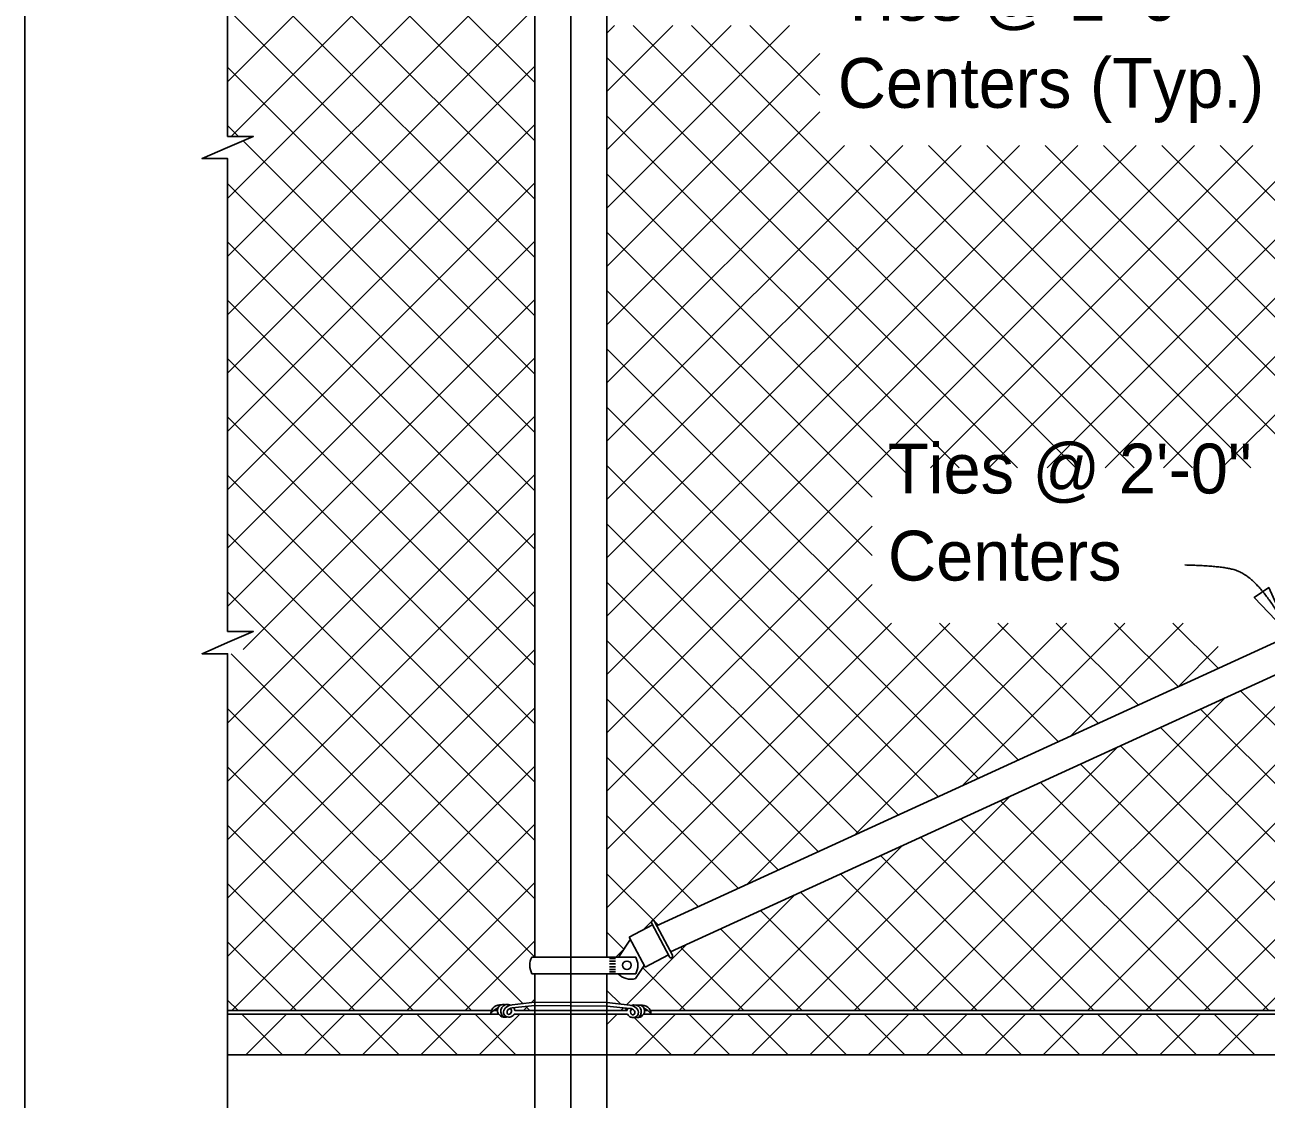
# Model space of a CAD drawing. Extents: x 0 to 41.2, y 0 to 26.
# Drawn here: x 0 to 5.02, y 17.29 to 21.63 of the extents above; entities that cross this region are included whole.
import ezdxf

# ---------------------------------------------------------------- set-up
doc = ezdxf.new("R2010")
doc.units = 0
for name, color, linetype in [('ActivePts-ConstElements', 7, 'Continuous'), ('CL_Major', 7, 'Continuous'), ('Dimension', 7, 'Continuous'), ('Miscellaneous', 7, 'Continuous'), ('Miscellaneous1', 7, 'Continuous'), ('SteelMisc', 7, 'Continuous'), ('SteelMisc_h', 7, 'Continuous'), ('SupstrConc', 7, 'Continuous'), ('TextStructures', 7, 'Continuous')]:
    doc.layers.add(name, color=color, linetype=linetype)

msp = doc.modelspace()

# ---------------------------------------------------------------- linework, layer by layer
at = {"layer": 'ActivePts-ConstElements'}
msp.add_lwpolyline([(0, 0), (41.2106, 0), (41.2106, 25.96), (0, 25.96)], close=True, dxfattribs=at)
at = {"layer": 'CL_Major'}
msp.add_line((2.2062, 25.6784), (2.2062, 14.8533), dxfattribs=at)
at = {"layer": 'Dimension'}
for points in [[(0.8194, 24.349), (0.8194, 21.1819), (0.9227, 21.1819), (0.8194, 21.1369), (0.716, 21.0919), (0.8194, 21.0919), (0.8194, 20.1983)], [(0.8194, 20.1983), (0.8194, 19.1806), (0.9227, 19.1806), (0.8194, 19.1356), (0.716, 19.0906), (0.8194, 19.0906), (0.8194, 16.8862)]]:
    msp.add_lwpolyline(points, dxfattribs=at)
msp.add_lwpolyline([(5.1135, 19.1655), (5.0266, 19.358), (4.968, 19.3186)], close=True, dxfattribs=at)
msp.add_open_spline([(4.6876, 19.4494), (4.8459, 19.4462), (4.9517, 19.4061), (5.0648, 19.263), (5.1136, 19.1655)], degree=2, dxfattribs=at)
at = {"layer": 'Miscellaneous'}
for p, q in [((1.8028, 22.3863), (0.8192, 21.4028)), ((2.0603, 21.1639), (0.8381, 22.3861)), ((2.0603, 21.3996), (1.0738, 22.3862)), ((6.6782, 22.39), (4.1304, 19.8423)), ((6.9139, 22.39), (4.3661, 19.8423)), ((7.1496, 22.39), (4.6018, 19.8423)), ((7.3853, 22.39), (4.8375, 19.8423)), ((2.0163, 22.3642), (0.8341, 21.1819)), ((2.0603, 22.1725), (0.8192, 20.9314)), ((2.0603, 20.9282), (0.8192, 22.1693)), ((2.0603, 21.9368), (0.8192, 20.6957)), ((2.0603, 20.6925), (0.8192, 21.9336)), ((2.0603, 21.701), (0.8192, 20.46)), ((2.0603, 20.4568), (0.8192, 21.6979)), ((2.6187, 21.6304), (2.352, 21.3636)), ((2.383, 21.6304), (2.352, 21.5993)), ((2.8544, 21.6304), (2.352, 21.1279)), ((3.0901, 21.6304), (2.352, 20.8922)), ((4.2468, 19.8423), (2.4587, 21.6304)), ((4.4825, 19.8423), (2.6944, 21.6304)), ((3.2122, 21.3482), (2.9301, 21.6304)), ((3.2122, 21.5167), (2.352, 20.6565)), ((4.011, 19.8423), (2.352, 21.5013)), ((2.0603, 21.4653), (0.8192, 20.2243)), ((2.0603, 20.2211), (0.8192, 21.4622)), ((3.2122, 21.281), (2.352, 20.4208)), ((2.0603, 21.2296), (0.8192, 19.9886)), ((0.8638, 21.1819), (0.8192, 21.2265)), ((3.7753, 19.8423), (2.352, 21.2656)), ((2.0603, 19.9854), (0.8817, 21.164)), ((4.2544, 21.1447), (2.352, 19.2423)), ((3.783, 21.1447), (2.352, 19.7137)), ((3.3116, 21.1447), (2.352, 20.1851)), ((3.5473, 21.1447), (2.352, 19.9494)), ((4.0187, 21.1447), (2.352, 19.478)), ((4.4901, 21.1447), (2.352, 19.0066)), ((4.7182, 19.8423), (3.4157, 21.1447)), ((4.7258, 21.1447), (3.4233, 19.8423)), ((4.9539, 19.8423), (3.6514, 21.1447)), ((4.9615, 21.1447), (3.659, 19.8423)), ((5.1896, 19.8423), (3.8871, 21.1447)), ((5.1972, 21.1447), (3.8947, 19.8423)), ((5.4253, 19.8423), (4.1228, 21.1447)), ((5.9529, 19.5503), (4.3585, 21.1447)), ((6.1145, 19.6244), (4.5942, 21.1447)), ((6.2762, 19.6985), (4.8299, 21.1447)), ((3.5642, 19.8177), (2.352, 21.0299)), ((2.0603, 20.9939), (0.8192, 19.7529)), ((2.0603, 19.7497), (0.8192, 20.9908)), ((3.4233, 19.7229), (2.352, 20.7942)), ((2.0603, 20.7582), (0.8192, 19.5171)), ((2.0603, 19.514), (0.8192, 20.7551)), ((2.0603, 20.5225), (0.8192, 19.2814)), ((2.0603, 19.2783), (0.8192, 20.5194)), ((3.4233, 19.4872), (2.352, 20.5585)), ((4.0136, 18.6612), (2.352, 20.3228)), ((2.0603, 19.0426), (0.8192, 20.2837)), ((2.0603, 20.2868), (0.8817, 19.1083)), ((3.852, 18.5871), (2.352, 20.0871)), ((7.463, 20.1106), (5.0009, 17.6486)), ((2.0603, 20.0511), (0.8192, 18.81)), ((2.0603, 18.8069), (0.8192, 20.048)), ((7.0277, 19.9111), (4.7652, 17.6486)), ((2.0603, 19.8154), (0.8192, 18.5743)), ((3.6903, 18.513), (2.352, 19.8514)), ((3.4233, 19.8423), (2.352, 18.7709)), ((2.0603, 18.5712), (0.8192, 19.8123)), ((6.5925, 19.7116), (4.5295, 17.6486)), ((3.5287, 18.439), (2.352, 19.6157)), ((2.0603, 19.5797), (0.8192, 18.3386)), ((2.0603, 18.3355), (0.8192, 19.5766)), ((3.4233, 19.6066), (2.352, 18.5352)), ((6.1573, 19.5121), (4.2938, 17.6486)), ((3.3671, 18.3649), (2.352, 19.38)), ((3.4233, 19.3709), (2.352, 18.2995)), ((2.0603, 19.344), (0.8192, 18.1029)), ((2.0603, 18.0998), (0.8192, 19.3409)), ((5.7221, 19.3126), (4.0581, 17.6486)), ((3.5027, 19.2146), (2.352, 18.0638)), ((3.7384, 19.2146), (2.4979, 17.974)), ((3.9741, 19.2146), (2.919, 18.1595)), ((4.2098, 19.2146), (3.3543, 18.359)), ((4.1752, 18.7353), (3.6959, 19.2146)), ((4.4455, 19.2146), (3.7895, 18.5585)), ((4.3368, 18.8094), (3.9317, 19.2146)), ((4.4984, 18.8835), (4.1674, 19.2146)), ((4.6812, 19.2146), (4.2247, 18.758)), ((4.66, 18.9576), (4.4031, 19.2146)), ((4.8216, 19.0317), (4.6388, 19.2146)), ((3.2055, 18.2908), (2.352, 19.1443)), ((5.2869, 19.1131), (3.8224, 17.6486)), ((4.8227, 19.1203), (4.6599, 18.9575)), ((2.0603, 19.1083), (0.8192, 17.8672)), ((2.0603, 17.8641), (0.8339, 19.0905)), ((4.8517, 18.9136), (3.5867, 17.6486)), ((6.2048, 17.6486), (4.912, 18.9413)), ((2.012, 17.6767), (0.8192, 18.8695)), ((2.0603, 18.8726), (0.8363, 17.6486)), ((3.0439, 18.2167), (2.352, 18.9086)), ((5.9691, 17.6486), (4.7504, 18.8672)), ((5.7333, 17.6486), (4.5888, 18.7931)), ((4.4165, 18.7141), (3.3509, 17.6486)), ((5.4976, 17.6486), (4.4272, 18.719)), ((2.8823, 18.1426), (2.352, 18.6729)), ((1.8044, 17.6486), (0.8192, 18.6338)), ((2.0603, 18.6369), (1.072, 17.6486)), ((5.2619, 17.6486), (4.2656, 18.6449)), ((5.0262, 17.6486), (4.104, 18.5708)), ((3.9813, 18.5146), (3.1152, 17.6486)), ((4.7905, 17.6486), (3.9424, 18.4967)), ((2.7207, 18.0685), (2.352, 18.4372)), ((4.5548, 17.6486), (3.7807, 18.4227)), ((1.5687, 17.6486), (0.8192, 18.3981)), ((2.0603, 18.4012), (1.3077, 17.6486)), ((3.5461, 18.3151), (2.8795, 17.6486)), ((4.3191, 17.6486), (3.6191, 18.3486)), ((4.0834, 17.6486), (3.4575, 18.2745)), ((1.333, 17.6486), (0.8192, 18.1624)), ((2.0603, 18.1655), (1.5434, 17.6486)), ((2.5591, 17.9944), (2.352, 18.2015)), ((3.8477, 17.6486), (3.2959, 18.2004)), ((3.1108, 18.1156), (2.6438, 17.6486)), ((3.612, 17.6486), (3.1343, 18.1263)), ((3.3763, 17.6486), (2.9727, 18.0522)), ((2.4208, 17.897), (2.352, 17.9658)), ((3.1406, 17.6486), (2.8111, 17.9781)), ((1.0973, 17.6486), (0.8192, 17.9267)), ((2.0603, 17.9298), (1.7791, 17.6486)), ((2.6756, 17.9161), (2.4309, 17.6713)), ((2.4207, 17.8968), (2.3885, 17.8646)), ((2.9049, 17.6486), (2.6494, 17.904)), ((2.6692, 17.6486), (2.4966, 17.8212)), ((2.4079, 17.6742), (2.352, 17.7301)), ((0.8616, 17.6486), (0.8192, 17.691)), ((2.0315, 17.6653), (2.0148, 17.6486)), ((2.0401, 17.6486), (2.0242, 17.6645)), ((2.0603, 17.6941), (2.0474, 17.6812)), ((2.4193, 17.6597), (2.4081, 17.6486)), ((2.4335, 17.6486), (2.4228, 17.6593)), ((0.8215, 17.6338), (0.8192, 17.6315)), ((1.0409, 17.4693), (0.8764, 17.6338)), ((1.0572, 17.6338), (0.8927, 17.4693)), ((1.2766, 17.4693), (1.1121, 17.6338)), ((1.2929, 17.6338), (1.1284, 17.4693)), ((1.5123, 17.4693), (1.3478, 17.6338)), ((1.5286, 17.6338), (1.3641, 17.4693)), ((1.748, 17.4693), (1.5835, 17.6338)), ((1.7643, 17.6338), (1.5998, 17.4693)), ((1.9837, 17.4693), (1.8192, 17.6338)), ((2, 17.6338), (1.8355, 17.4693)), ((2.0603, 17.6284), (2.0549, 17.6338)), ((2.3934, 17.6338), (2.352, 17.5924)), ((2.6127, 17.4693), (2.4617, 17.6203)), ((2.6291, 17.6338), (2.4646, 17.4693)), ((2.8484, 17.4693), (2.684, 17.6338)), ((2.8648, 17.6338), (2.7003, 17.4693)), ((3.0842, 17.4693), (2.9197, 17.6338)), ((3.1005, 17.6338), (2.936, 17.4693)), ((3.3199, 17.4693), (3.1554, 17.6338)), ((3.3362, 17.6338), (3.1717, 17.4693)), ((3.5556, 17.4693), (3.3911, 17.6338)), ((3.5719, 17.6338), (3.4074, 17.4693)), ((3.7913, 17.4693), (3.6268, 17.6338)), ((3.8076, 17.6338), (3.6431, 17.4693)), ((4.027, 17.4693), (3.8625, 17.6338)), ((4.0433, 17.6338), (3.8788, 17.4693)), ((4.2627, 17.4693), (4.0982, 17.6338)), ((4.279, 17.6338), (4.1145, 17.4693)), ((4.4984, 17.4693), (4.3339, 17.6338)), ((4.5147, 17.6338), (4.3502, 17.4693)), ((4.7341, 17.4693), (4.5696, 17.6338)), ((4.7504, 17.6338), (4.5859, 17.4693)), ((4.9698, 17.4693), (4.8053, 17.6338)), ((4.9861, 17.6338), (4.8216, 17.4693))]:
    msp.add_line(p, q, dxfattribs=at)
at = {"layer": 'Miscellaneous1'}
msp.add_lwpolyline([(0, 25.96), (41.2106, 25.96), (41.2106, 0), (0, 0)], close=True, dxfattribs=at)
at = {"layer": 'SteelMisc'}
for p, q in [((2.0603, 17.8646), (2.0603, 24.349)), ((2.352, 17.8646), (2.352, 24.349)), ((2.5526, 17.9915), (11.8021, 22.2317)), ((2.6096, 17.8858), (11.8582, 22.1255)), ((2.6171, 17.8717), (2.5446, 18.0088)), ((2.5369, 17.9947), (2.4426, 17.9448)), ((2.6052, 17.8654), (2.5328, 18.0026)), ((2.4468, 17.9368), (2.3999, 17.8651)), ((2.5063, 17.8242), (2.4426, 17.9448)), ((2.049, 17.8646), (2.4687, 17.8646)), ((2.3864, 17.8584), (2.3629, 17.8584)), ((2.5063, 17.8242), (2.6006, 17.8741)), ((2.3864, 17.8486), (2.3629, 17.8486)), ((2.3864, 17.8368), (2.3629, 17.8368)), ((2.3864, 17.825), (2.3629, 17.825)), ((2.3864, 17.8142), (2.3629, 17.8142)), ((2.5029, 17.8308), (2.4681, 17.7777)), ((2.0491, 17.7968), (2.4687, 17.7968)), ((2.0603, 17.0944), (2.0603, 17.7968)), ((2.352, 17.0944), (2.352, 17.7968)), ((2.3864, 17.8046), (2.3629, 17.8046)), ((2.0608, 17.6829), (1.9689, 17.6713)), ((2.0608, 17.6683), (1.9689, 17.6588)), ((2.352, 17.6812), (2.0608, 17.6829)), ((2.352, 17.6667), (2.0608, 17.6683)), ((2.352, 17.6812), (2.4449, 17.6695)), ((2.352, 17.6667), (2.4448, 17.657)), ((1.8859, 17.6486), (0.8192, 17.6486)), ((1.9145, 17.6338), (0.8192, 17.6338)), ((1.9096, 17.6486), (1.8943, 17.6486)), ((2.0603, 17.6338), (1.9773, 17.6338)), ((2.0603, 17.6486), (1.9799, 17.6486)), ((2.4342, 17.6486), (2.352, 17.6486)), ((2.4356, 17.6338), (2.352, 17.6338)), ((11.8982, 17.6338), (2.5005, 17.6338)), ((2.5172, 17.6486), (2.5041, 17.6486)), ((11.8969, 17.6486), (2.5271, 17.6486))]:
    msp.add_line(p, q, dxfattribs=at)
for centre, start, end in [((2.5385, 18.0058), 27.851, 207.851), ((2.611, 17.8686), 207.851, 27.851)]:
    msp.add_arc(centre, 0.00673, start, end, dxfattribs=at)
for centre, major_axis, ratio, start_param, end_param in [((2.1181, 17.8309), (-0.0776, 0), 0.957868, 5.811591, 6.758603), ((2.3995, 17.8309), (0.0776, 0), 0.957868, 5.810211, 6.75616), ((2.4515, 17.846), (-0.0647, -0.0342), 0.957868, 0.271397, 1.331255), ((1.9209, 17.6361), (0.0373, 0), 0.957868, 1.427863, 3.108042), ((1.942, 17.5964), (-0.0724, 0), 0.957868, 5.133134, 5.652106), ((1.9345, 17.648), (-0.0249, 0), 0.957868, 5.913851, 7.104804), ((1.9333, 17.6505), (0.023, 0), 0.957868, 1.234085, 2.861055), ((1.9521, 17.6452), (0.0295, 0), 0.957868, 1.132635, 3.996184), ((1.9656, 17.647), (-0.0303, -0.0108), 0.724765, 4.35367, 6.224248), ((1.9706, 17.634), (-0.0259, 0), 0.957868, 4.777514, 5.646371), ((1.9549, 17.6463), (0.0119, 0), 0.957868, 5.725876, 7.416677), ((1.9551, 17.6451), (0.0251, 0), 0.957868, 0.146361, 0.642491), ((2.4586, 17.6433), (-0.0251, 0), 0.957868, 5.640601, 6.061443), ((2.4431, 17.6323), (0.0259, 0), 0.957868, 0.636815, 1.505671), ((2.4482, 17.6452), (0.0303, -0.0108), 0.724765, 0.058937, 1.929515), ((2.4617, 17.6434), (-0.0295, 0), 0.957868, 2.287002, 5.15055), ((2.4804, 17.6488), (-0.023, 0), 0.957868, 3.422131, 5.0491), ((2.4929, 17.6343), (-0.0373, 0), 0.957868, 3.175144, 4.855322), ((2.4718, 17.5946), (0.0724, 0), 0.957868, 0.631079, 1.150052), ((1.9359, 17.644), (0.0231, 0), 0.957868, 3.795406, 4.839145), ((1.942, 17.6383), (0.0206, -0.0021), 0.798607, 4.329004, 5.170153), ((1.9554, 17.6383), (0.0206, -0.0021), 0.798607, 3.319435, 5.221193), ((1.9623, 17.6429), (-0.0139, 0), 0.957868, 5.822914, 6.905413), ((1.9566, 17.6405), (-0.00795, 0), 0.957868, 0.785393, 2.999691), ((1.9481, 17.6571), (0.0391, 0), 0.957868, 5.134108, 5.414681), ((1.9549, 17.6463), (0.0119, 0), 0.957868, 5.639684, 5.723117), ((1.9551, 17.6451), (0.0251, 0), 0.957868, 5.523427, 5.795636), ((2.4586, 17.6433), (-0.0251, 0), 0.957868, 0.405384, 0.751829), ((2.4657, 17.6553), (-0.0391, 0), 0.957868, 0.863445, 1.149077), ((2.4589, 17.6445), (-0.0119, 0), 0.957868, 5.149694, 6.840495), ((2.4589, 17.6445), (-0.0119, 0), 0.957868, 0.560069, 0.643501), ((2.4572, 17.6387), (0.00795, 0), 0.957868, 3.283493, 6.243757), ((2.4583, 17.6366), (-0.0206, -0.0021), 0.798607, 1.063032, 2.96375), ((2.4515, 17.6411), (0.0139, 0), 0.957868, 6.080589, 6.743456), ((2.4718, 17.6366), (-0.0206, -0.0021), 0.798607, 1.113032, 1.956656), ((2.4779, 17.6423), (-0.0231, 0), 0.957868, 1.44404, 2.503632), ((2.4793, 17.6463), (0.0249, 0), 0.957868, 5.476514, 6.65252)]:
    msp.add_ellipse(centre, major_axis=major_axis, ratio=ratio, start_param=start_param, end_param=end_param, dxfattribs=at)
msp.add_ellipse((2.4328, 17.8313), major_axis=(-0.0178, 0), ratio=0.957868, dxfattribs=at)
at = {"layer": 'SteelMisc_h'}
for p, q in [((2.352, 17.6486), (2.0603, 17.6486)), ((2.352, 17.6338), (2.0603, 17.6338))]:
    msp.add_line(p, q, dxfattribs=at)
at = {"layer": 'SupstrConc'}
msp.add_line((0.8193, 17.4693), (5.3495, 17.4693), dxfattribs=at)

# ---------------------------------------------------------------- texts
at = {"layer": 'TextStructures'}
for s, p in [('Ties @ 1\'-0" ', (3.285, 21.6493)), ('Centers (Typ.)', (3.285, 21.2973)), ('Ties @ 2\'-0" ', (3.4877, 19.7385)), ('Centers', (3.4877, 19.3865))]:
    msp.add_text(s, height=0.2016, dxfattribs=at).set_placement(p)

doc.saveas('drawing.dxf')
